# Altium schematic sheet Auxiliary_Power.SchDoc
size A3
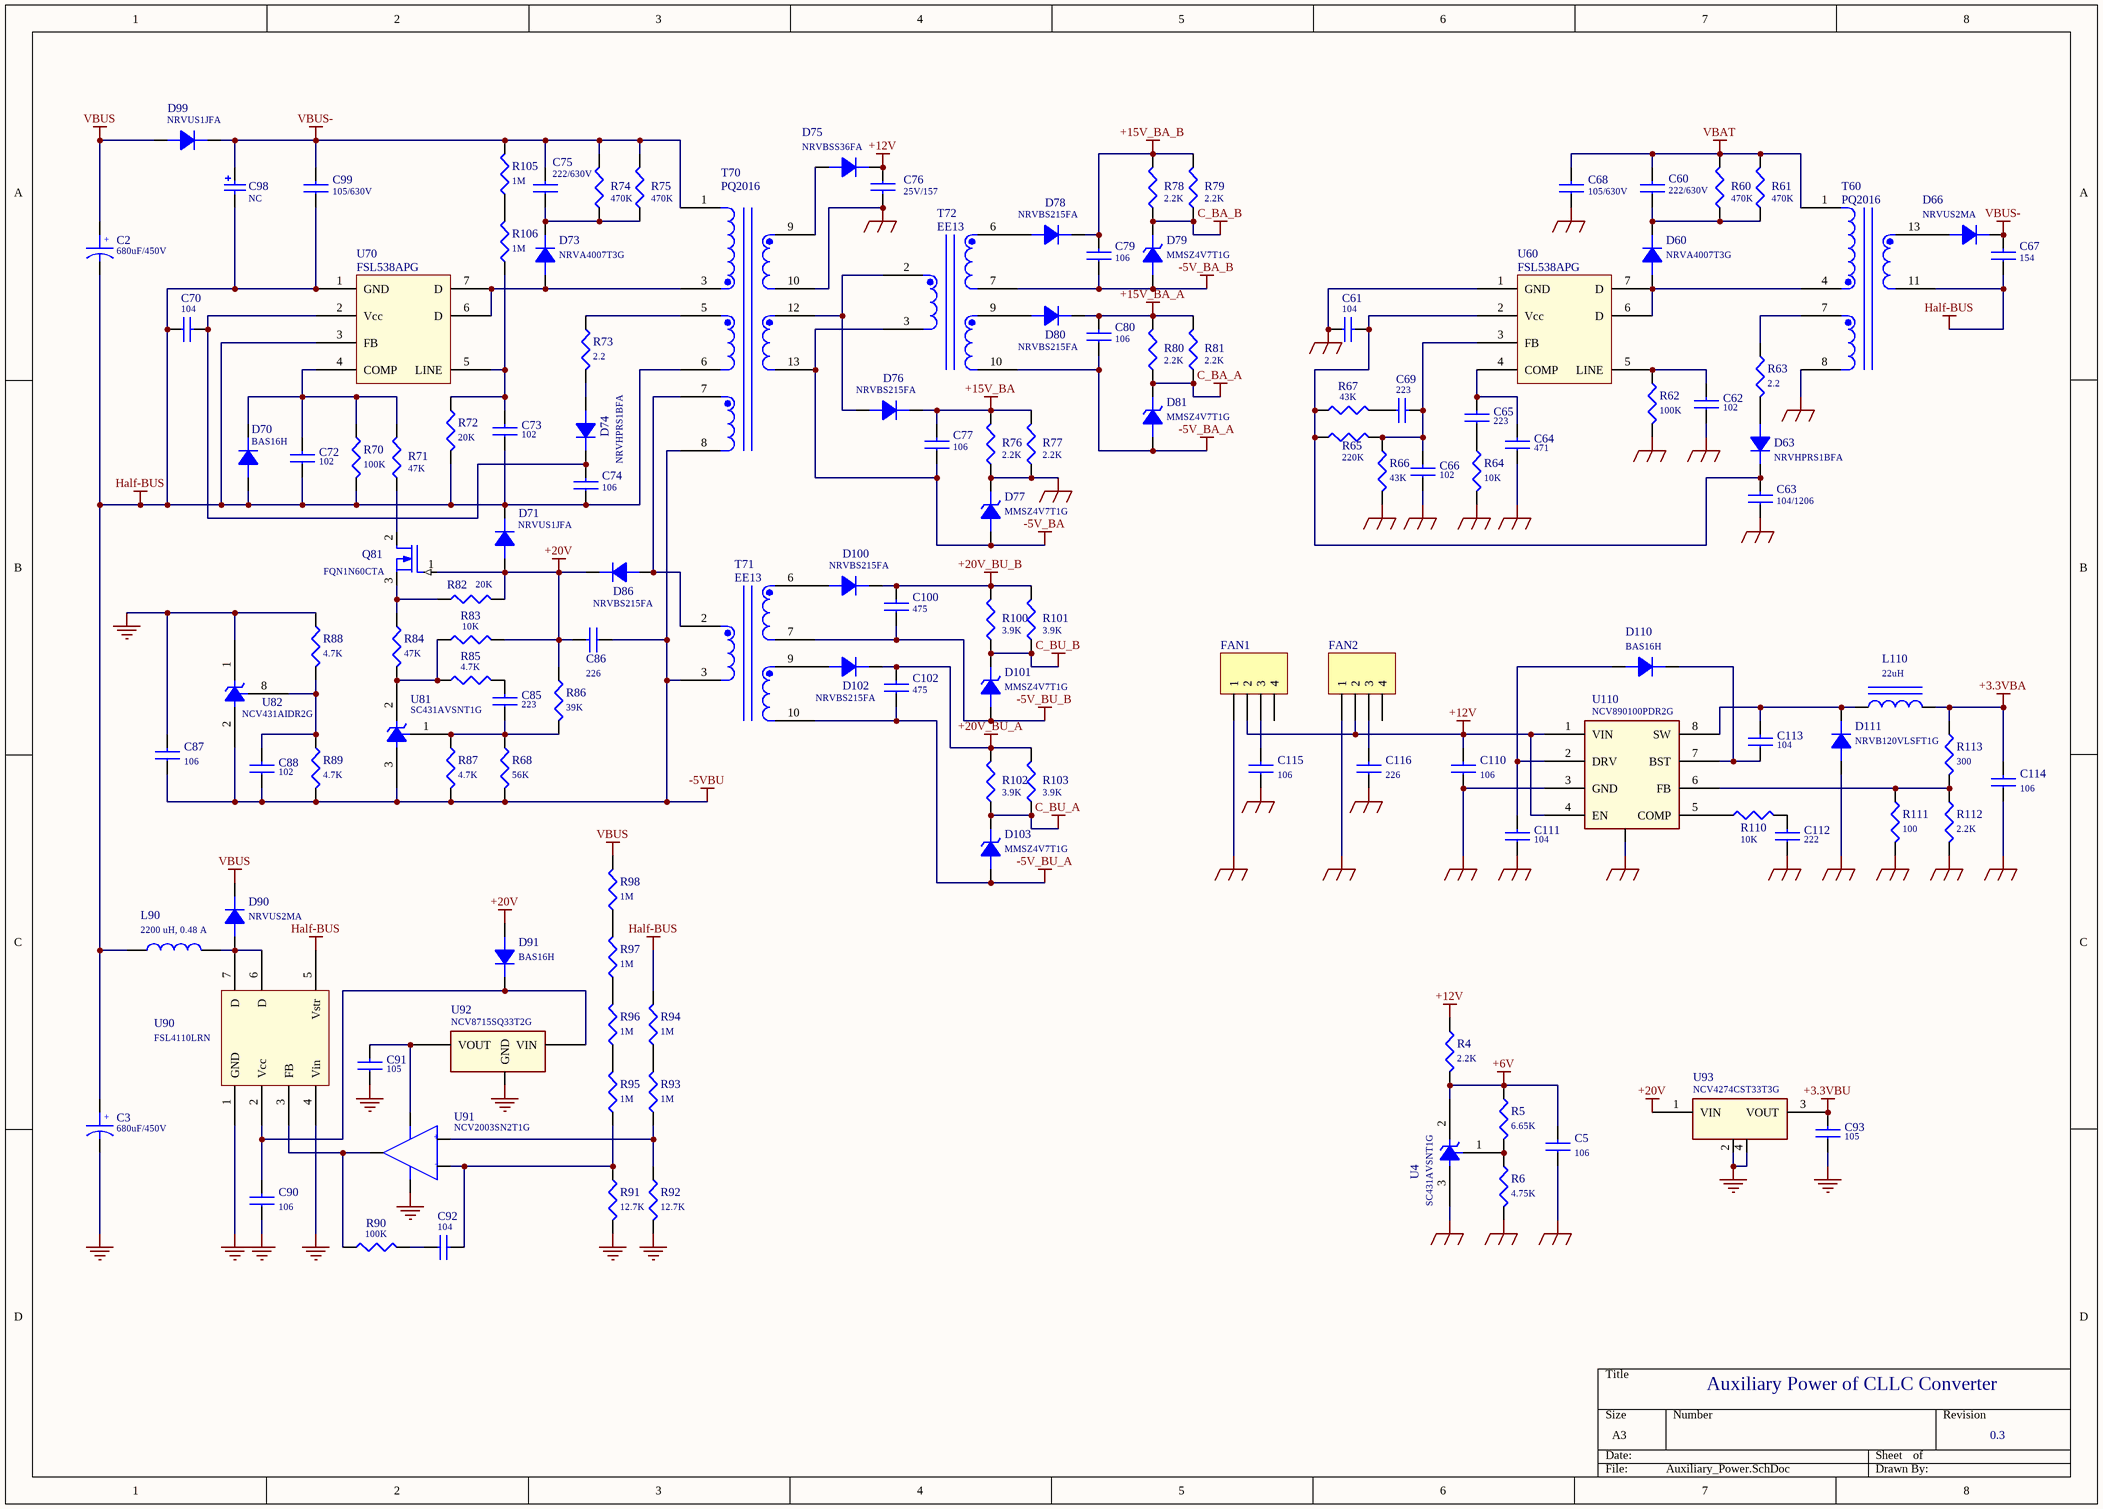
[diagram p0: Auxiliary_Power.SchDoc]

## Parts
C2  680uF/450V  [WCAP-AI3H_35x57]
C3  680uF/450V  [WCAP-AI3H_35x57]
C5  106  [SMT_1206_CM]
C60  222/630V  [SMT_1206_CM]
C61  104  [SMT_0805_CM]
C62  102  [SMT_0805_CM]
C63  104/1206  [SMT_1206_CM]
C64  471  [SMT_0805_CM]
C65  223  [SMT_0805_CM]
C66  102  [SMT_0805_CM]
C67  154  [SMT_1210]
C68  105/630V  [CAP2220]
C69  223  [SMT_0805_CM]
C70  104  [SMT_0805_CM]
C72  102  [SMT_0805_CM]
C73  102  [SMT_0805_CM]
C74  106  [SMT_1206_CM]
C75  222/630V  [SMT_1206_CM]
C76  25V/157  [CAP2220_3]
C77  106  [SMT_1206_CM]
C79  106  [SMT_1206_CM]
C80  106  [SMT_1206_CM]
C85  223  [SMT_0805_CM]
C86  226  [SMT_1210]
C87  106  [SMT_1206_CM]
C88  102  [SMT_0805_CM]
C90  106  [SMT_1206_CM]
C91  105  [SMT_0805_CM]
C92  104  [SMT_0805_CM]
C93  105  [SMT_0805_CM]
C98  NC  [WCAP-ATG5_10x25]
C99  105/630V  [CAP2220]
C100  475  [SMT_1206_CM]
C102  475  [SMT_1206_CM]
C110  106  [SMT_1206_CM]
C111  104  [SMT_0805_CM]
C112  222  [SMT_0805_CM]
C113  104  [SMT_0805_CM]
C114  106  [SMT_1206_CM]
C115  106  [SMT_1206_CM]
C116  226  [SMT_1210]
D60  NRVA4007T3G  [DO-214AC(SMA)]
D63  NRVHPRS1BFA  [SOD-123FL]
D66  NRVUS2MA  [DO-214AC(SMA)]
D70  BAS16H  [SOD-323M]
D71  NRVUS1JFA  [SOD-123FL]
D73  NRVA4007T3G  [DO-214AC(SMA)]
D74  NRVHPRS1BFA  [SOD-123FL]
D75  NRVBSS36FA  [SOD-123FL]
D76  NRVBS215FA  [SOD-123FL]
D77  MMSZ4V7T1G  [SOD-123FL]
D78  NRVBS215FA  [SOD-123FL]
D79  MMSZ4V7T1G  [SOD-123FL]
D80  NRVBS215FA  [SOD-123FL]
D81  MMSZ4V7T1G  [SOD-123FL]
D86  NRVBS215FA  [SOD-123FL]
D90  NRVUS2MA  [DO-214AC(SMA)]
D91  BAS16H  [SOD-323M]
D99  NRVUS1JFA  [SOD-123FL]
D100  NRVBS215FA  [SOD-123FL]
D101  MMSZ4V7T1G  [SOD-123FL]
D102  NRVBS215FA  [SOD-123FL]
D103  MMSZ4V7T1G  [SOD-123FL]
D110  BAS16H  [SOD-323M]
D111  NRVB120VLSFT1G  [SOD-123FL]
FAN1  (no value)  [XH-4A]
FAN2  (no value)  [XH-4A]
L90  2200 uH, 0.48 A  [WE-TI_1014_Standard]
L110  22uH  [INDUCTOR-7*7*3.5]
Q81  FQN1N60CTA  [TO92a]
R4  2.2K  [SMT_0805_RM]
R5  6.65K  [SMT_0805_RM]
R6  4.75K  [SMT_0805_RM]
R60  470K  [SMT_1206_RM]
R61  470K  [SMT_1206_RM]
R62  100K  [SMT_0805_RM]
R63  2.2  [SMT_0805_RM]
R64  10K  [SMT_0805_RM]
R65  220K  [SMT_0805_RM]
R66  43K  [SMT_0805_RM]
R67  43K  [SMT_0805_RM]
R68  56K  [SMT_0805_RM]
R70  100K  [SMT_0805_RM]
R71  47K  [SMT_1206_RM]
R72  20K  [SMT_0805_RM]
R73  2.2  [SMT_0805_RM]
R74  470K  [SMT_1206_RM]
R75  470K  [SMT_1206_RM]
R76  2.2K  [SMT_1206_RM]
R77  2.2K  [SMT_1206_RM]
R78  2.2K  [SMT_1206_RM]
R79  2.2K  [SMT_1206_RM]
R80  2.2K  [SMT_1206_RM]
R81  2.2K  [SMT_1206_RM]
R82  20K  [SMT_0805_RM]
R83  10K  [SMT_0805_RM]
R84  47K  [SMT_1206_RM]
R85  4.7K  [SMT_0805_RM]
R86  39K  [SMT_0805_RM]
R87  4.7K  [SMT_0805_RM]
R88  4.7K  [SMT_0805_RM]
R89  4.7K  [SMT_0805_RM]
R90  100K  [SMT_0805_RM]
R91  12.7K  [SMT_0805_RM]
R92  12.7K  [SMT_0805_RM]
R93  1M  [SMT_1206_RM]
R94  1M  [SMT_1206_RM]
R95  1M  [SMT_1206_RM]
R96  1M  [SMT_1206_RM]
R97  1M  [SMT_1206_RM]
R98  1M  [SMT_1206_RM]
R100  3.9K  [SMT_1206_RM]
R101  3.9K  [SMT_1206_RM]
R102  3.9K  [SMT_1206_RM]
R103  3.9K  [SMT_1206_RM]
R105  1M  [SMT_1206_RM]
R106  1M  [SMT_1206_RM]
R110  10K  [SMT_0805_RM]
R111  100  [SMT_0805_RM]
R112  2.2K  [SMT_0805_RM]
R113  300  [SMT_0805_RM]
T60  PQ2016  [Trans_PQ2016_14P]
T70  PQ2016  [Trans_PQ2016_14P]
T71  EE13  [Trans_EE13_6_6_10Pin_V]
T72  EE13  [Trans_EE13_6_6_10Pin_V]
U4  SC431AVSNT1G  [SOT-23-3L]
U60  FSL538APG  [DIP7]
U70  FSL538APG  [DIP7]
U81  SC431AVSNT1G  [SOT-23-3L]
U82  NCV431AIDR2G  [Sop8]
U90  FSL4110LRN  [DIP7]
U91  NCV2003SN2T1G  [SOT-23-5L]
U92  NCV8715SQ33T2G  [SC70-5]
U93  NCV4274CST33T3G  [SOT-223]
U110  NCV890100PDR2G  [SOIC8E]

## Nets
+3.3VBA: C114.2 L110.2 R113.1
+3.3VBU: C93.2 U93.3(VOUT)
+6V: C5.2 R4.2 R5.1 U4.2(K)
+12V: C76.1 C110.2 D75.2(K) FAN1.2 FAN2.2 R4.1 U110.1(VIN) U110.4(EN)
+15V_BA: C77.2 D76.2(K) R76.2 R77.2
+15V_BA_A: C80.2 D80.2(K) R80.2 R81.2
+15V_BA_B: C79.2 D78.2(K) R78.2 R79.2
+20V: C86.2 D71.1(A) D86.2(K) D91.1(A) Q81.1(GATE) R82.2 R83.2 R86.1 U93.1(VIN)
+20V_BU_A: C102.2 D102.2(K) R102.2 R103.2
+20V_BU_B: C100.2 D100.2(K) R100.2 R101.2
-5V_BA: C77.1 D77.1(ANODE) T70.13 T72.3
-5V_BA_A: C80.1 D81.1(ANODE) T72.10
-5V_BA_B: C79.1 D79.1(ANODE) T72.7
-5V_BU_A: C102.1 D103.1(ANODE) T71.10
-5V_BU_B: C100.1 D101.1(ANODE) T71.7
-5VBU: C86.1 C87.1 C88.1 R68.2 R87.2 R89.2 T70.8 T71.3 U81.3(A) U82.2(A)
C_BA_A: D81.2(CATHODE) R80.1 R81.1
C_BA_B: D79.2(CATHODE) R78.1 R79.1
C_BU_A: D103.2(CATHODE) R102.1 R103.1
C_BU_B: D101.2(CATHODE) R100.1 R101.1
GND: C5.1 C61.1 C62.1 C63.1 C64.1 C66.1 C68.1 C76.2 C110.1 C111.1 C112.1 C114.1 C115.1 C116.1 D77.2(CATHODE) D111.1(A) FAN1.1 FAN2.1 R6.2 R62.2 R64.2 R66.2 R76.1 R77.1 R111.2 R112.2 T60.8 T70.10 U4.3(A) U60.1(GND) U110.3(GND) U110.9(PAD)
Half-BUS: C2.2 C3.1 C67.1 C70.1 C72.1 C73.1 C74.1 C98.1(N) C99.1 D70.1(A) D71.2(K) L90.1 R70.2 R72.2 R94.2 T60.11 T70.6 U70.1(GND) U70.3(FB) U90.5(Vstr)
PGND: C3.2 C87.2 C90.1 C91.1 C93.1 R88.1 R91.2 R92.2 U82.1(K) U90.1(GND) U90.4(Vin) U91.2(GND) U92.2(GND) U93.2(GND) U93.4(GND)
VBAT: C60.2 C68.2 R60.2 R61.2 T60.1
VBUS: C2.1 D90.2(K) D99.1(A) R98.2
VBUS-: C67.2 C75.2 C98.2(P) C99.2 D66.2(K) D99.2(K) R74.2 R75.2 R105.2 T70.1
NetC60_1: C60.1 D60.2(K) R60.1 R61.1
NetC61_2: C61.2 C63.2 D63.2(K) R65.1 R67.1 U60.2(Vcc)
NetC62_2: C62.2 R62.1 U60.5(LINE)
NetC64_2: C64.2 C65.2 U60.4(COMP)
NetC65_1: C65.1 R64.1
NetC66_2: C66.2 C69.2 R65.2 R66.1 U60.3(FB)
NetC69_1: C69.1 R67.2
NetC70_2: C70.2 C74.2 D74.2(K) U70.2(Vcc)
NetC72_2: C72.2 D70.2(K) R70.1 R71.2 U70.4(COMP)
NetC73_2: C73.2 R72.1 R106.1 U70.5(LINE)
NetC75_1: C75.1 D73.2(K) R74.1 R75.1
NetC85_1: C85.1 R68.1 R86.2 R87.1 U81.1(REF)
NetC85_2: C85.2 R85.2
NetC88_2: C88.2 R88.2 R89.1 U82.8(REF)
NetC90_2: C90.2 D91.2(K) U90.2(Vcc) U92.4(VIN)
NetC91_2: C91.2 U91.5(VCC) U92.5(VOUT)
NetC92_1: C92.1 R90.2
NetC92_2: C92.2 R91.1 R95.1 U91.4(-IN)
NetC111_2: C111.2 D110.1(A) U110.2(DRV)
NetC112_2: C112.2 R110.2
NetC113_1: C113.1 D110.2(K) U110.7(BST)
NetC113_2: C113.2 D111.2(K) L110.1 U110.8(SW)
NetC115_2: C115.2 FAN1.3
NetC116_2: C116.2 FAN2.3
NetD60_1: D60.1(A) T60.4 U60.6(D) U60.7(D)
NetD63_1: D63.1(A) R63.2
NetD66_1: D66.1(A) T60.13
NetD73_1: D73.1(A) T70.3 U70.6(D) U70.7(D)
NetD74_1: D74.1(A) R73.2
NetD75_1: D75.1(A) T70.9
NetD76_1: D76.1(A) T70.12 T72.2
NetD78_1: D78.1(A) T72.6
NetD80_1: D80.1(A) T72.9
NetD86_1: D86.1(A) T70.7 T71.2
NetD90_1: D90.1(A) L90.2 U90.6(D) U90.7(D)
NetD100_1: D100.1(A) T71.6
NetD102_1: D102.1(A) T71.9
NetQ81_2: Q81.2(DRAIN) R71.1
NetQ81_3: Q81.3(SOURCE) R82.1 R84.1
NetR5_2: R5.2 R6.1 U4.1(REF)
NetR63_1: R63.1 T60.7
NetR73_1: R73.1 T70.5
NetR83_1: R83.1 R84.2 R85.1 U81.2(K)
NetR90_1: R90.1 U90.3(FB) U91.1(OUT)
NetR92_1: R92.1 R93.1 U91.3(+IN)
NetR93_2: R93.2 R94.1
NetR95_2: R95.2 R96.1
NetR96_2: R96.2 R97.1
NetR97_2: R97.2 R98.1
NetR105_1: R105.1 R106.2
NetR110_1: R110.1 U110.5(COMP)
NetR111_1: R111.1 R112.1 R113.2 U110.6(FB)

Not connected (* = marked no-connect by the designer): FAN1 4; FAN2 4

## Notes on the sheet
- Auxiliary Power of CLLC Converter
- 0.3

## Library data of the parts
C2 C3 = CAP POL
C5 C60 C61 C63 C67-C70 C74-C77 C79 C80 C86 C87 C90 C92 C99 C100 C102 C110 C114-C116 = CAP NP
C62 C64-C66 C72 C73 C85 C88 C91 C93 C111-C113 = CAP_0805
C98 = 860021375012: WCAP-ATG5 THT Aluminum Electrolytic Capacitors, D10mm x L25mm, 22uF, +/-20%, 400VDC; Dissipation Factor: 15%; Endurance: 2000h; Leakage Current: 264uA; Ripple Current max.: 162mA; Technical Reference: ATJF250220M400DSPAAB000
D60 D63 D66 D70 D71 D73-D76 D78 D80 D86 D90 D91 D99 D100 D102 D110 D111 = DIODE
D77 D79 D81 D101 D103 = DIODE ZENER
FAN1 FAN2 = Header 4: Header, 4-Pin
L90 = 7447480222: Radial Leaded Wire Wound Inductor WE-TI, size 1014, 2200 uH, 0.48 A; Rated Current: 0.48 A; Inductance: 2200 uH; DC Resistance max.: 2.5 Ohm; Self Resonant Frequency: 0.83 MHz; Saturation Current: 0.56 A; Type: Standard
L110 = INDUCTOR IRON
Q81 = MOSFET N: R187: C158
R4-R6 R60-R66 R68 R70-R81 R84 R86-R89 R91-R98 R100-R103 R105 R106 R110-R113 = R
R67 R82 R83 R85 R90 = R_0805
T60 = Transformer_3_Winding
T70 = Transformer_5_winding
T71 T72 = Transformer_Pulse_1_to_2
U4 U81 U82 = TL431
U60 U70 = FSL538
U90 = FSL4110
U91 = LM383/TO220_1
U92 = LDO_SC70-5
U93 = LDO_SOT223
U110 = NCV890200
